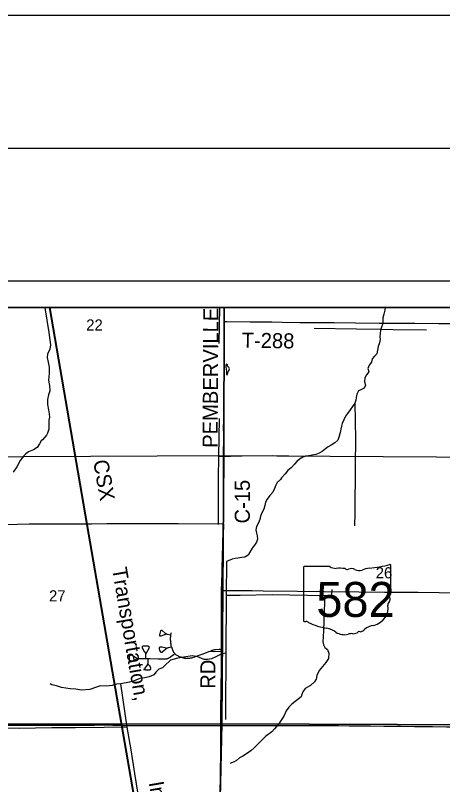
# Model space of a CAD drawing. Extents: x -8.3 to 42.1, y 0 to 22.
# Drawn here: x 5.158 to 6.765, y 19.103 to 22 of the extents above; entities that cross this region are included whole.
import ezdxf

# ---------------------------------------------------------------- set-up
doc = ezdxf.new("R2010")
doc.units = 0
for name, color, linetype in [('Default', 7, 'Continuous'), ('GM_X_County_Road', 7, 'Continuous'), ('GM_X_County_Road_Text', 7, 'Continuous'), ('GM_X_Minor_Lake', 7, 'Continuous'), ('GM_X_Minor_River', 7, 'Continuous'), ('GM_X_Rail_Line', 7, 'Continuous'), ('GM_X_Rail_Line_Text', 7, 'Continuous'), ('GM_X_Section', 7, 'Continuous'), ('GM_X_Section_Text', 7, 'Continuous'), ('GM_X_State_Location', 7, 'Continuous'), ('GM_X_State_Route', 7, 'Continuous'), ('GM_X_State_Shield', 7, 'Continuous'), ('GM_X_Township_Road', 7, 'Continuous'), ('GM_X_Township_Road_Text', 7, 'Continuous'), ('SH_Border', 7, 'Continuous'), ('SH_Cut_Line', 7, 'Continuous'), ('SH_Data', 7, 'Continuous')]:
    doc.layers.add(name, color=color, linetype=linetype)

msp = doc.modelspace()

# ---------------------------------------------------------------- linework, layer by layer
at = {"layer": 'Default'}
for points in [[(5.9435, 20.9), (4.9425, 20.9), (4.9373, 20.3372), (5.9413, 20.342)], [(6.9477, 20.9), (5.9435, 20.9), (5.9413, 20.342), (6.941, 20.3362)]]:
    msp.add_lwpolyline(points, close=True, dxfattribs=at)
at = {"layer": 'GM_X_County_Road'}
for points in [[(5.9435, 20.847), (5.9438, 20.8785), (5.9441, 20.9)], [(5.9402, 20.0853), (5.94, 20.1243), (5.9404, 20.1572), (5.9403, 20.1734), (5.9406, 20.2126), (5.9409, 20.2616), (5.9409, 20.3357), (5.9412, 20.419), (5.9411, 20.4501), (5.9413, 20.4706), (5.9414, 20.4867), (5.9414, 20.5184), (5.9417, 20.5589), (5.942, 20.5905), (5.943, 20.6518), (5.943, 20.6773), (5.9429, 20.7767), (5.9434, 20.8333), (5.9435, 20.847)], [(5.9328, 19.8339), (5.9349, 19.8975), (5.9355, 19.9149), (5.937, 19.9655), (5.938, 20.0033), (5.9386, 20.0249), (5.9391, 20.041), (5.9402, 20.0853)], [(5.9326, 19.6046), (5.9327, 19.6129), (5.9329, 19.625), (5.9328, 19.6518), (5.9328, 19.6878), (5.9326, 19.7133), (5.9326, 19.7276), (5.9325, 19.755), (5.9327, 19.7958), (5.9328, 19.8339)], [(5.9308, 19.3255), (5.9308, 19.3336), (5.9309, 19.3788), (5.9318, 19.4646), (5.9324, 19.5423), (5.9327, 19.5834), (5.9326, 19.6039), (5.9326, 19.6046)], [(5.9228, 18.8176), (5.9236, 18.8554), (5.9249, 18.9064), (5.9252, 18.9313), (5.9259, 18.9698), (5.9269, 19.0114), (5.9281, 19.0742), (5.9293, 19.1308), (5.9298, 19.1731), (5.93, 19.1942), (5.9306, 19.2452), (5.9307, 19.308), (5.9308, 19.3255)]]:
    msp.add_lwpolyline(points, dxfattribs=at)
at = {"layer": 'GM_X_Minor_Lake'}
msp.add_line((5.9507, 20.6665), (5.9521, 20.66), dxfattribs=at)
msp.add_lwpolyline([(5.9521, 20.66), (5.9515, 20.6509), (5.9514, 20.6479), (5.954, 20.6463), (5.956, 20.6501), (5.9577, 20.6584), (5.9601, 20.6617), (5.9629, 20.6685), (5.9604, 20.6735), (5.9567, 20.6774), (5.9561, 20.6842), (5.9524, 20.687), (5.9496, 20.6817), (5.9499, 20.6764), (5.9507, 20.6665)], dxfattribs=at)
at = {"layer": 'GM_X_Minor_River'}
msp.add_line((5.9244, 20.7636), (5.9269, 20.9), dxfattribs=at)
for points in [[(5.2688, 20.9), (5.2701, 20.8913), (5.2839, 20.8056), (5.2903, 20.7595), (5.2876, 20.7433), (5.2784, 20.7234), (5.277, 20.7113), (5.2804, 20.6941), (5.2848, 20.675), (5.2854, 20.6519), (5.2839, 20.6371), (5.2829, 20.6273), (5.283, 20.6182), (5.2857, 20.6056), (5.2871, 20.5854), (5.2826, 20.5707), (5.2791, 20.553), (5.279, 20.534), (5.2823, 20.5142), (5.285, 20.4997), (5.2866, 20.4868), (5.284, 20.4758), (5.284, 20.4599), (5.2839, 20.4409), (5.2786, 20.4262), (5.2747, 20.4191), (5.2595, 20.4013), (5.2545, 20.3976), (5.2481, 20.3856), (5.2402, 20.3725), (5.226, 20.3641), (5.2072, 20.3566), (5.1976, 20.3485), (5.1894, 20.3404), (5.1757, 20.3236), (5.163, 20.3), (5.15, 20.2791)], [(6.5488, 20.9), (6.5467, 20.8897), (6.5436, 20.8746), (6.5403, 20.861), (6.5396, 20.8492), (6.5389, 20.836), (6.5352, 20.8262), (6.5316, 20.8145), (6.5293, 20.802), (6.529, 20.7888), (6.5292, 20.7789), (6.5269, 20.766), (6.5228, 20.7529), (6.5198, 20.7393), (6.5176, 20.7257), (6.5083, 20.716), (6.4993, 20.706), (6.4975, 20.6935), (6.4878, 20.6827), (6.484, 20.6703), (6.4875, 20.6577), (6.4785, 20.6458), (6.4718, 20.6342), (6.4703, 20.6202), (6.4749, 20.6071), (6.4701, 20.5959), (6.4574, 20.5897), (6.4479, 20.5862), (6.4426, 20.5734), (6.44, 20.5602), (6.4386, 20.5503), (6.4346, 20.5398), (6.4259, 20.5264), (6.4165, 20.5141), (6.4064, 20.5007), (6.3997, 20.4902), (6.3933, 20.4767), (6.3872, 20.4624), (6.3843, 20.4522), (6.3818, 20.442), (6.3792, 20.4284), (6.3751, 20.4145), (6.3702, 20.4006), (6.3589, 20.3895), (6.3454, 20.3807), (6.3336, 20.3753), (6.3239, 20.3675), (6.3119, 20.3572), (6.3004, 20.3514), (6.2874, 20.3464), (6.2737, 20.343), (6.2608, 20.3414), (6.2494, 20.3394), (6.2394, 20.3362), (6.2264, 20.3285), (6.2159, 20.3201), (6.2077, 20.3096), (6.1945, 20.2963), (6.1825, 20.2852), (6.1724, 20.2733), (6.1586, 20.2579), (6.1544, 20.2517), (6.1428, 20.2402), (6.1376, 20.2301), (6.1324, 20.2185), (6.1256, 20.2046), (6.1147, 20.1912), (6.1045, 20.1778), (6.0985, 20.1662), (6.0956, 20.1541)], [(6.7039, 20.8145), (6.5789, 20.816), (6.5312, 20.8164), (6.4407, 20.8175), (6.2818, 20.8202)], [(6.4346, 20.5398), (6.4369, 20.4035), (6.436, 20.3052), (6.4341, 20.1239), (6.4337, 20.0772)], [(5.9211, 20.082), (5.9216, 20.2558), (5.9233, 20.3385), (5.925, 20.4819)], [(5.9233, 20.3385), (6.0108, 20.341), (6.1252, 20.342), (6.2494, 20.3394)], [(6.0956, 20.1541), (6.0918, 20.1405), (6.0846, 20.1259), (6.0798, 20.1143), (6.0772, 20.101), (6.0716, 20.0886), (6.0648, 20.0748), (6.0626, 20.0627), (6.0649, 20.0497), (6.067, 20.0398), (6.0678, 20.0276), (6.0652, 20.0152), (6.0566, 20.0044), (6.048, 19.9932), (6.0397, 19.9782), (6.0333, 19.9662), (6.0203, 19.959), (6.0089, 19.9577), (5.9948, 19.9554), (5.9849, 19.9545), (5.9735, 19.9517), (5.9517, 19.9435)], [(5.9517, 19.9435), (5.9508, 19.8145), (5.9496, 19.5979), (5.9485, 19.3873), (5.9483, 19.3474)], [(6.3475, 19.8372), (6.3462, 19.816), (6.3219, 19.8135), (6.1254, 19.8171), (6.0028, 19.8153), (5.9508, 19.8145)], [(6.3219, 19.8135), (6.3186, 19.7586), (6.3167, 19.6801), (6.3145, 19.6399), (6.3165, 19.6285), (6.3216, 19.6196), (6.3317, 19.6118), (6.3362, 19.5976), (6.3353, 19.5772), (6.3259, 19.5626), (6.3123, 19.5477), (6.2998, 19.5325), (6.2921, 19.5141), (6.2895, 19.4993), (6.2832, 19.4892), (6.2677, 19.4763), (6.2481, 19.4647), (6.2394, 19.4516), (6.235, 19.4418), (6.2329, 19.4332), (6.2148, 19.4188), (6.1974, 19.4059), (6.1858, 19.3948), (6.1763, 19.3803), (6.1671, 19.3607), (6.1553, 19.3417), (6.1486, 19.3312), (6.1319, 19.313), (6.1221, 19.3015), (6.0989, 19.2842), (6.0733, 19.259), (6.0559, 19.2416), (6.0427, 19.2302), (6.0238, 19.2166), (6.0127, 19.21), (6.0011, 19.2031), (5.9899, 19.1939), (5.9807, 19.188), (5.9704, 19.1845), (5.9658, 19.1819)], [(5.9496, 19.5979), (5.9317, 19.5945), (5.9114, 19.584), (5.8949, 19.5761), (5.8808, 19.5741), (5.8679, 19.5741), (5.8443, 19.5837), (5.8221, 19.5873), (5.7913, 19.5827), (5.7688, 19.5783), (5.7406, 19.5718), (5.7185, 19.5496), (5.7108, 19.5426), (5.6974, 19.5368), (5.6873, 19.5276), (5.6787, 19.5164), (5.6614, 19.5081), (5.6439, 19.5043), (5.6257, 19.5017), (5.605, 19.4939), (5.5871, 19.4886), (5.5544, 19.4826), (5.5377, 19.4803), (5.5213, 19.4758), (5.4989, 19.4737), (5.4781, 19.475), (5.4628, 19.4693), (5.4383, 19.4611), (5.4065, 19.4589), (5.3854, 19.4624), (5.3638, 19.4629), (5.3317, 19.4686), (5.3129, 19.474), (5.2953, 19.4786), (5.2881, 19.4818)], [(5.755, 18.2292), (5.7321, 18.3713), (5.6995, 18.5714), (5.6614, 18.8072), (5.6319, 18.9882), (5.6066, 19.144), (5.5933, 19.2339), (5.5787, 19.3184), (5.5544, 19.4826)], [(5.5787, 19.3184), (5.492, 19.3175), (5.3833, 19.3167), (5.2943, 19.3166), (5.1719, 19.3139), (5.0602, 19.3158), (4.9307, 19.3155), (4.8496, 19.3145), (4.8398, 19.317), (4.8299, 19.3149), (4.8172, 19.3054), (4.7975, 19.2914), (4.7764, 19.2802), (4.7519, 19.2667), (4.6992, 19.2358), (4.6735, 19.222), (4.659, 19.2174), (4.6453, 19.2154), (4.5948, 19.2094)]]:
    msp.add_lwpolyline(points, dxfattribs=at)
at = {"layer": 'GM_X_Rail_Line'}
for points in [[(5.9654, 16.7643), (5.9567, 16.8335), (5.932, 17.0379), (5.9087, 17.2246), (5.8981, 17.3081), (5.8822, 17.4435), (5.8389, 17.6857), (5.7322, 18.3104), (5.5565, 19.3262), (5.427, 20.0822), (5.2858, 20.9)], [(6.2899, 14.1), (6.2222, 14.6512), (6.0176, 16.3351), (5.9781, 16.679), (5.9602, 16.8313), (5.9345, 17.0381), (5.9111, 17.2249), (5.9006, 17.3084), (5.8846, 17.4439), (5.8413, 17.6862), (5.7347, 18.3108), (5.559, 19.3267), (5.4294, 20.0826), (5.2883, 20.9)]]:
    msp.add_lwpolyline(points, dxfattribs=at)
at = {"layer": 'GM_X_Section'}
for points in [[(5.9413, 20.342), (5.9346, 19.331), (4.9315, 19.3303), (4.9373, 20.3372)], [(6.941, 20.3362), (6.9241, 19.3275), (5.9346, 19.331), (5.9413, 20.342)], [(5.9346, 19.331), (5.9121, 18.3219), (5.8932, 18.3221), (4.9147, 18.3251), (4.9315, 19.3303)], [(6.9241, 19.3275), (6.9034, 18.3155), (6.8731, 18.3158), (5.9121, 18.3219), (5.9346, 19.331)]]:
    msp.add_lwpolyline(points, close=True, dxfattribs=at)
at = {"layer": 'GM_X_State_Route'}
for points in [[(4.9318, 20.083), (4.9352, 20.0829), (4.9551, 20.0827), (5.0816, 20.0829), (5.1657, 20.0839), (5.2092, 20.0844), (5.2453, 20.0844), (5.3111, 20.085), (5.3434, 20.0854), (5.3862, 20.0851), (5.4229, 20.0852), (5.4437, 20.0853), (5.5021, 20.0855), (5.5524, 20.0856), (5.6084, 20.0857), (5.6531, 20.0858), (5.77, 20.0858), (5.9402, 20.0853)], [(5.9402, 20.0853), (5.9391, 20.041), (5.9386, 20.0249), (5.938, 20.0033), (5.937, 19.9655), (5.9355, 19.9149), (5.9349, 19.8975), (5.9328, 19.8339)], [(5.9328, 19.8339), (5.9678, 19.8338), (6.0144, 19.8334), (6.0486, 19.8332), (6.0902, 19.8326), (6.2183, 19.8312), (6.319, 19.8297), (6.4489, 19.8283), (6.5458, 19.8277), (6.5943, 19.8277), (6.6733, 19.8275), (6.7517, 19.8266), (6.8635, 19.8255)]]:
    msp.add_lwpolyline(points, dxfattribs=at)
at = {"layer": 'GM_X_State_Shield'}
for p, q in [((6.2408, 19.9201), (6.2408, 19.72)), ((6.3406, 19.9235), (6.2441, 19.9235)), ((6.5704, 19.8238), (6.5704, 19.9285)), ((6.5704, 19.8238), (6.5704, 19.8238))]:
    msp.add_line(p, q, dxfattribs=at)
for centre, major_axis, start_param, end_param in [((6.2446, 19.9205), (0.00382, 0), 1.712693, 3.28349), ((6.3636, 19.9467), (0.037, 0), 4.042523, 4.731795), ((6.3758, 19.8112), (0.133, 0), 1.404758, 1.657858), ((6.406, 19.9215), (0.0107, 0), 3.836095, 5.185415), ((6.4217, 19.8984), (0.0222, 0), 0.950623, 2.079405), ((6.4504, 19.9301), (0.0267, 0), 4.081561, 5.145723), ((6.4976, 19.8624), (0.0703, 0), 1.699011, 2.107814), ((6.453, 20.1963), (0.3495, 0), 4.814394, 5.042369), ((6.5667, 19.9289), (0.00367, 0), 6.141152, 7.989035), ((6.5696, 19.8161), (0.00568, 0), 1.883978, 3.671073), ((6.5665, 19.8234), (0.00393, 0), 5.05454, 6.418171), ((6.5835, 19.78), (0.0248, 0), 2.387724, 3.262537), ((6.5334, 19.8029), (0.0341, 0), 5.934695, 6.695948), ((6.4726, 19.7667), (0.0874, 0), 5.101752, 6.440018), ((6.2446, 19.7195), (0.00385, 0), 3.00124, 4.508301), ((6.2452, 19.74), (0.0294, 0), 4.665946, 4.897461), ((6.2512, 19.7084), (0.0106, 0), 0.519207, 1.627899), ((6.385, 19.8882), (0.2524, 0), 4.195997, 4.488961), ((6.3098, 19.63), (0.079, 0), 0.823519, 1.323587), ((6.3952, 19.7074), (0.0501, 0), 4.026481, 4.996735), ((6.4278, 19.6924), (0.0267, 0), 4.691044, 5.507374), ((6.452, 19.673), (0.00752, 0), 1.147584, 2.315152), ((6.4488, 19.7006), (0.0282, 0), 4.937069, 5.64225), ((6.5094, 19.6638), (0.0479, 0), 1.647645, 2.488434), ((6.4242, 19.6382), (0.0412, 0), 1.495662, 1.94098)]:
    msp.add_ellipse(centre, major_axis=major_axis, ratio=0.8, start_param=start_param, end_param=end_param, dxfattribs=at)
at = {"layer": 'GM_X_Township_Road'}
msp.add_line((5.6481, 19.5774), (5.6566, 19.5773), dxfattribs=at)
for points in [[(7.9572, 20.9), (3.9382, 20.9)], [(5.9435, 20.847), (5.9532, 20.8469), (6.0414, 20.846), (6.0713, 20.8459), (6.1229, 20.8452), (6.1607, 20.8445), (6.2279, 20.8437), (6.2695, 20.8434), (6.2979, 20.8433), (6.3563, 20.8427), (6.4371, 20.8419), (6.5254, 20.8411), (6.5665, 20.8407), (6.615, 20.8405), (6.6604, 20.8406), (6.7499, 20.84), (6.827, 20.8388), (6.9491, 20.836)], [(5.7241, 19.6706), (5.7194, 19.6673), (5.7178, 19.6664), (5.7152, 19.6653), (5.705, 19.6615), (5.7037, 19.6613), (5.703, 19.6612), (5.7023, 19.6613), (5.7016, 19.6617), (5.701, 19.6624), (5.7007, 19.6633), (5.7007, 19.6644), (5.7012, 19.6673), (5.7051, 19.6818), (5.7053, 19.6825), (5.706, 19.6833), (5.7066, 19.6837), (5.7077, 19.6838), (5.7084, 19.6837), (5.7094, 19.6832), (5.7102, 19.6826), (5.7217, 19.6729), (5.7231, 19.6718), (5.7248, 19.6707), (5.7262, 19.67), (5.7277, 19.6695), (5.7301, 19.6689), (5.7367, 19.6676), (5.7414, 19.6665)], [(5.7431, 19.6739), (5.7423, 19.6715), (5.7418, 19.669), (5.7414, 19.6665)], [(5.7414, 19.6665), (5.7412, 19.6646), (5.7406, 19.6578), (5.7404, 19.6548), (5.7404, 19.6519), (5.7405, 19.6475), (5.7407, 19.6444), (5.7411, 19.6403), (5.7414, 19.6366), (5.7418, 19.6328), (5.7424, 19.6294), (5.7429, 19.6263), (5.744, 19.6231), (5.7445, 19.6219)], [(5.6481, 19.5774), (5.6479, 19.5912), (5.648, 19.5927), (5.6482, 19.5937), (5.6487, 19.5951), (5.6492, 19.5965), (5.661, 19.6171), (5.6613, 19.618), (5.6615, 19.6187), (5.6616, 19.6197), (5.6616, 19.6203), (5.6614, 19.621), (5.661, 19.6216), (5.6605, 19.622), (5.66, 19.6225), (5.6593, 19.6229), (5.6584, 19.6234), (5.6574, 19.6237), (5.6563, 19.624), (5.6551, 19.6242), (5.6418, 19.6242), (5.6389, 19.6239), (5.6381, 19.6238), (5.6371, 19.6235), (5.6363, 19.6231), (5.6354, 19.6222), (5.6348, 19.621), (5.6346, 19.6202), (5.6345, 19.6195), (5.6346, 19.6187), (5.6348, 19.6178), (5.6353, 19.6165), (5.6359, 19.6154), (5.6425, 19.6043), (5.6486, 19.5961)], [(5.7249, 19.6168), (5.7224, 19.6129), (5.7215, 19.6116), (5.7206, 19.6104), (5.7171, 19.6072), (5.7101, 19.6013), (5.7092, 19.6007), (5.7085, 19.6004), (5.7078, 19.6003), (5.7071, 19.6003), (5.7064, 19.6005), (5.7058, 19.6008), (5.7051, 19.6013), (5.7044, 19.6022), (5.7036, 19.6033), (5.7028, 19.6045), (5.7019, 19.6064), (5.7011, 19.6083), (5.7005, 19.61), (5.7, 19.612), (5.6997, 19.6136), (5.6996, 19.6149), (5.6995, 19.6162), (5.6995, 19.6171), (5.6997, 19.6182), (5.7, 19.6191), (5.7003, 19.6196), (5.7007, 19.6202), (5.7013, 19.6207), (5.7023, 19.6212), (5.7034, 19.6216), (5.7049, 19.6219), (5.7066, 19.6221), (5.7079, 19.622), (5.7093, 19.6218), (5.7251, 19.6172), (5.7264, 19.617), (5.7275, 19.6169), (5.7289, 19.617), (5.7301, 19.6172), (5.7339, 19.6185), (5.7389, 19.6201), (5.7445, 19.6219)], [(5.7445, 19.6219), (5.7461, 19.6176), (5.749, 19.6107), (5.753, 19.6017), (5.7538, 19.6005), (5.7547, 19.599), (5.7557, 19.5976), (5.757, 19.5961)], [(5.615, 19.5782), (5.6127, 19.575), (5.6116, 19.574), (5.6106, 19.5734), (5.6098, 19.5729), (5.6015, 19.5683), (5.5945, 19.565), (5.5935, 19.5648), (5.5924, 19.5646), (5.5914, 19.5646), (5.5905, 19.5648), (5.5897, 19.5651), (5.5889, 19.5655), (5.5882, 19.566), (5.5877, 19.5666), (5.5873, 19.5672), (5.5871, 19.568), (5.5868, 19.5692), (5.5867, 19.5729), (5.5872, 19.5851), (5.5874, 19.5869), (5.5877, 19.5879), (5.5881, 19.5886), (5.5887, 19.5895), (5.5893, 19.5901), (5.5901, 19.5906), (5.5909, 19.5909), (5.5918, 19.5911), (5.5929, 19.5912), (5.5941, 19.5911), (5.5952, 19.5909), (5.5962, 19.5905), (5.6031, 19.5865), (5.6144, 19.5791), (5.6155, 19.5785), (5.6164, 19.5781), (5.6174, 19.5779), (5.6188, 19.5777), (5.6481, 19.5774)], [(5.6566, 19.5773), (5.6648, 19.5771), (5.6946, 19.5766), (5.7219, 19.5764), (5.7244, 19.5766), (5.7268, 19.5769), (5.7287, 19.5773), (5.7306, 19.578), (5.732, 19.5786), (5.7338, 19.5794), (5.7355, 19.5803), (5.7375, 19.5814), (5.7408, 19.5836), (5.7474, 19.5885), (5.7532, 19.5931), (5.757, 19.5961)], [(5.757, 19.5961), (5.7583, 19.5949), (5.7603, 19.5931), (5.7623, 19.5917), (5.7646, 19.5902), (5.7669, 19.5889), (5.77, 19.5873), (5.7731, 19.5859), (5.7765, 19.5844), (5.7794, 19.5833), (5.7821, 19.5824), (5.7847, 19.5817), (5.7877, 19.5808), (5.7904, 19.5801), (5.7923, 19.5797), (5.7943, 19.5793), (5.7968, 19.579), (5.7992, 19.5788), (5.8018, 19.5787), (5.8055, 19.5786), (5.8089, 19.5787), (5.812, 19.5789), (5.8144, 19.5791), (5.8167, 19.5795), (5.8193, 19.5799), (5.8214, 19.5804), (5.8257, 19.5814), (5.8322, 19.5834), (5.8457, 19.5883), (5.8642, 19.5955), (5.8859, 19.6034), (5.891, 19.6052)], [(5.891, 19.6052), (5.8981, 19.6086), (5.9003, 19.6095), (5.9032, 19.6104), (5.9065, 19.6112), (5.9099, 19.6117), (5.924, 19.6128), (5.9327, 19.6129)], [(5.891, 19.6052), (5.9039, 19.6044), (5.9274, 19.6046), (5.9326, 19.6046)], [(5.6562, 19.5566), (5.6585, 19.5545), (5.6597, 19.553), (5.6621, 19.5494), (5.6642, 19.5456), (5.6657, 19.5424), (5.6662, 19.5413), (5.6665, 19.5402), (5.6667, 19.539), (5.6666, 19.5382), (5.6665, 19.5374), (5.6663, 19.5368), (5.6659, 19.5362), (5.665, 19.5351), (5.6644, 19.5347), (5.6636, 19.5344), (5.6628, 19.5341), (5.6613, 19.5339), (5.6498, 19.5337), (5.6489, 19.5338), (5.6481, 19.5341), (5.6472, 19.5345), (5.6465, 19.5351), (5.6461, 19.5356), (5.6458, 19.5363), (5.6456, 19.5372), (5.6456, 19.5381), (5.6458, 19.5391), (5.646, 19.54), (5.6464, 19.5408), (5.6553, 19.5554), (5.6559, 19.557), (5.6564, 19.5584), (5.6567, 19.5599), (5.6569, 19.5614), (5.6568, 19.5712), (5.6566, 19.5773)], [(4.9236, 19.3267), (4.9492, 19.3268), (5.0269, 19.3269), (5.1512, 19.3265), (5.2134, 19.3261), (5.3004, 19.3259), (5.4558, 19.3268), (5.5024, 19.3272), (5.5242, 19.327), (5.5398, 19.3267), (5.5553, 19.3261), (5.5615, 19.3258), (5.5832, 19.3252), (5.5987, 19.3249), (5.6484, 19.3246), (5.6919, 19.3247), (5.7603, 19.3252), (5.8318, 19.3254), (5.8722, 19.3254), (5.9126, 19.3256), (5.9308, 19.3255)], [(5.9308, 19.3255), (5.9468, 19.3255), (5.9841, 19.3255), (6.0183, 19.3255), (6.1116, 19.3256), (6.1613, 19.3256), (6.2266, 19.3251), (6.2887, 19.3249), (6.3385, 19.3252), (6.3727, 19.3249), (6.4131, 19.3244), (6.4939, 19.3236), (6.5436, 19.3229), (6.6058, 19.3224), (6.6586, 19.322), (6.727, 19.3212), (6.7798, 19.3207), (6.8234, 19.3201), (6.8824, 19.3189), (6.9073, 19.3184), (6.9227, 19.3185), (6.928, 19.3188)]]:
    msp.add_lwpolyline(points, dxfattribs=at)
at = {"layer": 'SH_Border'}
msp.add_lwpolyline([(1.5, 21.5), (33.5, 21.5), (33.5, 0.5), (1.5, 0.5)], close=True, dxfattribs=at)
at = {"layer": 'SH_Cut_Line'}
msp.add_lwpolyline([(0, 0), (34, 0), (34, 22), (0, 22)], close=True, dxfattribs=at)
msp.add_lwpolyline([(7.9572, 20.9), (2.1, 20.9)], dxfattribs=at)
at = {"layer": 'SH_Data'}
for p, q in [((2, 21), (9, 21)), ((2.1, 20.9), (8.9, 20.9))]:
    msp.add_line(p, q, dxfattribs=at)

# ---------------------------------------------------------------- texts
at = {"layer": 'GM_X_County_Road_Text'}
for s, height, rotation, p in [('PEMBERVILLE', 0.056818, 89.7019, (5.9185, 20.3709)), ('C-15', 0.05682, 90, (6.0396, 20.086)), ('RD', 0.05682, 90, (5.9102, 19.4635))]:
    msp.add_text(s, height=height, rotation=rotation, dxfattribs=at).set_placement(p)
at = {"layer": 'GM_X_Rail_Line_Text'}
for s, height, rotation, p in [('CSX', 0.05663, 279.8998, (5.45, 20.3214)), ('Transportation,', 0.056629, 279.7939, (5.5204, 19.9164)), ('Inc.', 0.05663, 279.7937, (5.6589, 19.1104))]:
    msp.add_text(s, height=height, rotation=rotation, dxfattribs=at).set_placement(p)
at = {"layer": 'GM_X_Section_Text'}
for s, p in [('22', (5.4242, 20.813)), ('26', (6.513, 19.8794)), ('27', (5.2842, 19.7927))]:
    msp.add_text(s, height=0.04186, rotation=0, dxfattribs=at).set_placement(p)
at = {"layer": 'GM_X_State_Location'}
msp.add_text('582', height=0.000189, rotation=0, dxfattribs=at).set_placement((6.335, 19.7929))
for s in ['s', 'r']:
    msp.add_text(s, height=0.000189, dxfattribs=at).set_placement((6.4019, 19.8067))
at = {"layer": 'GM_X_State_Shield'}
msp.add_text('582', height=0.13184, dxfattribs=at).set_placement((6.2898, 19.7341))
at = {"layer": 'GM_X_Township_Road_Text'}
msp.add_text('T-288', height=0.05682, rotation=359.1594, dxfattribs=at).set_placement((6.0084, 20.7482))

doc.saveas('drawing.dxf')
